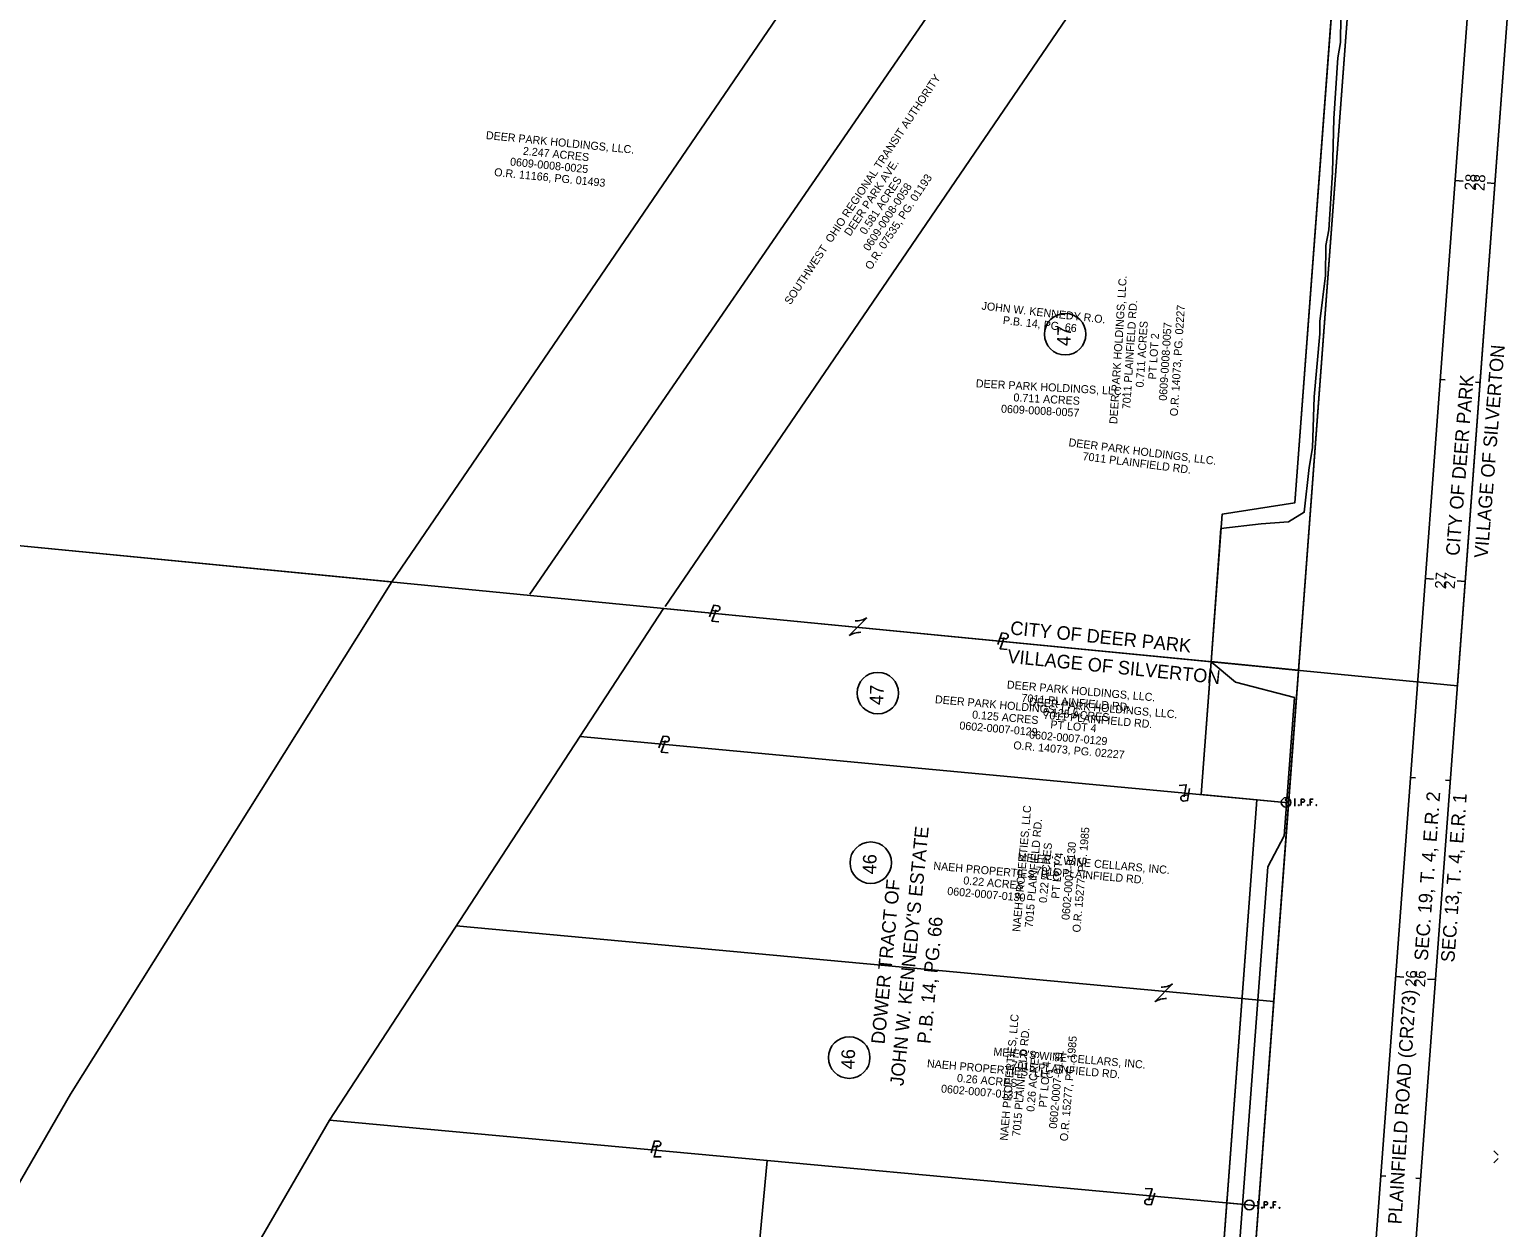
# Model space of a CAD drawing. Extents: x 204354 to 231038, y 361459 to 365260.
# Drawn here: x 220294.5 to 220662.5, y 363095.8 to 363396 of the extents above; entities that cross this region are included whole.
import ezdxf

# ---------------------------------------------------------------- set-up
doc = ezdxf.new("R2010")
doc.units = 0
for name, color, linetype in [('CM_Corridor_Point_Control', 7, 'Continuous'), ('CM_Corridor_Range_Conceptual', 7, 'Continuous'), ('Default', 7, 'Continuous'), ('DT_P_Contour_Minor', 7, 'Continuous'), ('DT_P_Contour_Text', 7, 'Continuous'), ('DT_P_Triangles', 7, 'Continuous'), ('DT_P_Void', 7, 'Continuous'), ('DT_X_Contour_Minor', 7, 'Continuous'), ('MD_P_CURB_BACK_BOT', 7, 'Continuous'), ('MD_P_Intersection_MatchLine', 7, 'Continuous'), ('MD_P_Surface_Asphalt_Concrete_Base', 7, 'Continuous'), ('MD_P_Surface_Asphalt_Concrete_Intermediate_Course', 7, 'Continuous'), ('MD_P_Surface_Finished_Grade', 7, 'Continuous'), ('MD_P_SW_BOT', 7, 'Continuous'), ('MD_P_SW_TOP', 7, 'Continuous'), ('PV_P_Curb', 7, 'Continuous'), ('PV_P_EOP', 7, 'Continuous'), ('PV_P_Walk', 7, 'Continuous'), ('SC_Shading1', 7, 'Continuous')]:
    doc.layers.add(name, color=color, linetype=linetype)

msp = doc.modelspace()

# ---------------------------------------------------------------- linework, layer by layer
at = {"layer": 'CM_Corridor_Range_Conceptual'}
for q in [(220713.48, 364052.43), (220697.45, 363837.56)]:
    msp.add_line((220572.38, 362161.22), q, dxfattribs=at)
at = {"layer": 'Default'}
msp.add_line((220562.24, 362159.63), (220675.24, 363674.28), dxfattribs=at)
at = {"layer": 'DT_P_Contour_Text'}
for centre in [(220553.98, 363319.59), (220507.05, 363229.68), (220505.28, 363187.2), (220499.88, 363138.37)]:
    msp.add_circle(centre, 5.2, dxfattribs=at)
at = {"layer": 'DT_P_Triangles'}
msp.add_lwpolyline([(220623.04, 363399.23), (220622.97, 363392.65), (220622.23, 363388.84), (220621.3, 363373.66), (220620.92, 363360.07), (220620.04, 363345.75), (220619.25, 363341.79), (220619.14, 363334.27), (220617.73, 363322.8), (220617.8, 363319.71), (220616.37, 363303.87), (220615.88, 363291.11), (220615.07, 363286.19), (220613.87, 363275), (220609.92, 363272.56), (220603.08, 363272.1), (220593, 363270.9), (220590.51, 363237.55), (220596.67, 363232.4), (220611.41, 363228.61), (220608.82, 363193.91), (220604.73, 363186.19), (220595.67, 363064.69)], dxfattribs=at)
at = {"layer": 'MD_P_CURB_BACK_BOT'}
for p, q in [((220661.62, 363357.35), (220659.63, 363357.49)), ((220657.9, 363307.48), (220656.71, 363307.57)), ((220654.18, 363257.62), (220652.19, 363257.77)), ((220650.46, 363207.76), (220649.27, 363207.85)), ((220646.74, 363157.9), (220644.75, 363158.05)), ((220643.02, 363108.04), (220641.83, 363108.13))]:
    msp.add_line(p, q, dxfattribs=at)
at = {"layer": 'MD_P_Intersection_MatchLine'}
for p, q in [((220611.53, 363277.39), (220626.27, 363475)), ((220611.53, 363277.39), (220626.27, 363475)), ((220593.27, 363274.47), (220611.53, 363277.39)), ((220590.51, 363237.47), (220593.27, 363274.47)), ((220588.03, 363204.27), (220590.51, 363237.56)), ((220612.41, 363235.32), (220590.51, 363237.56)), ((220612.41, 363235.42), (220590.52, 363237.56)), ((220588.03, 363204.27), (220609.94, 363202.23)), ((220594.43, 363101.93), (220601.97, 363202.98)), ((220594.43, 363101.93), (220601.97, 363202.97)), ((220589.36, 363033.98), (220594.53, 363103.29)), ((220594.43, 363101.95), (220602.4, 363101.21))]:
    msp.add_line(p, q, dxfattribs=at)
at = {"layer": 'MD_P_Surface_Asphalt_Concrete_Base'}
for p, q in [((220661.32, 363115.01), (220662.42, 363113.92)), ((220661.32, 363111.99), (220662.42, 363113.09))]:
    msp.add_line(p, q, dxfattribs=at)
at = {"layer": 'MD_P_Surface_Asphalt_Concrete_Intermediate_Course'}
for p, q in [((220652.24, 363231.63), (220712.17, 364034.87)), ((220048.52, 363290.31), (220652.24, 363231.54))]:
    msp.add_line(p, q, dxfattribs=at)
at = {"layer": 'MD_P_Surface_Finished_Grade'}
msp.add_line((220609.3, 363202.42), (220609.3, 363201.53), dxfattribs=at)
for points in [[(220611.33, 363203.1), (220611.69, 363203.1)], [(220611.51, 363201.5), (220611.51, 363203.1)], [(220613.08, 363201.5), (220613.08, 363203.1), (220613.61, 363203.1), (220613.66, 363203.09), (220613.74, 363203.06), (220613.77, 363203.04), (220613.8, 363203.01), (220613.85, 363202.95), (220613.88, 363202.89), (220613.9, 363202.78), (220613.9, 363202.63), (220613.89, 363202.58), (220613.87, 363202.51), (220613.83, 363202.42), (220613.78, 363202.38), (220613.75, 363202.36), (220613.69, 363202.33), (220613.61, 363202.32), (220613.08, 363202.32)], [(220616.09, 363203.1), (220615.32, 363203.1), (220615.32, 363201.5)], [(220611.33, 363201.5), (220611.69, 363201.5)], [(220612.47, 363201.71), (220612.52, 363201.71), (220612.56, 363201.69), (220612.59, 363201.64), (220612.59, 363201.58), (220612.56, 363201.53), (220612.52, 363201.5), (220612.47, 363201.5), (220612.44, 363201.53), (220612.4, 363201.58), (220612.4, 363201.64), (220612.44, 363201.69), (220612.47, 363201.71)], [(220614.72, 363201.71), (220614.77, 363201.71), (220614.81, 363201.69), (220614.84, 363201.64), (220614.84, 363201.58), (220614.81, 363201.53), (220614.77, 363201.5), (220614.72, 363201.5), (220614.69, 363201.53), (220614.65, 363201.58), (220614.65, 363201.64), (220614.69, 363201.69), (220614.72, 363201.71)], [(220615.32, 363202.32), (220615.86, 363202.32)], [(220616.87, 363201.71), (220616.92, 363201.71), (220616.96, 363201.69), (220616.99, 363201.64), (220616.99, 363201.58), (220616.96, 363201.53), (220616.92, 363201.5), (220616.87, 363201.5), (220616.83, 363201.53), (220616.8, 363201.58), (220616.8, 363201.64), (220616.83, 363201.69), (220616.87, 363201.71)], [(220602.1, 363102.24), (220602.46, 363102.24)], [(220602.1, 363100.64), (220602.46, 363100.64)], [(220602.28, 363100.64), (220602.28, 363102.24)], [(220603.24, 363100.86), (220603.29, 363100.86), (220603.33, 363100.83), (220603.36, 363100.78), (220603.36, 363100.72), (220603.33, 363100.67), (220603.29, 363100.64), (220603.24, 363100.64), (220603.21, 363100.67), (220603.17, 363100.72), (220603.17, 363100.78), (220603.21, 363100.83), (220603.24, 363100.86)], [(220603.85, 363100.64), (220603.85, 363102.24), (220604.37, 363102.24), (220604.43, 363102.23), (220604.51, 363102.2), (220604.54, 363102.18), (220604.57, 363102.15), (220604.62, 363102.09), (220604.65, 363102.03), (220604.67, 363101.93), (220604.67, 363101.77), (220604.66, 363101.72), (220604.64, 363101.65), (220604.59, 363101.56), (220604.55, 363101.52), (220604.52, 363101.5), (220604.46, 363101.47), (220604.37, 363101.46), (220603.85, 363101.46)], [(220605.49, 363100.86), (220605.54, 363100.86), (220605.58, 363100.83), (220605.61, 363100.78), (220605.61, 363100.72), (220605.58, 363100.67), (220605.54, 363100.64), (220605.49, 363100.64), (220605.45, 363100.67), (220605.42, 363100.72), (220605.42, 363100.78), (220605.45, 363100.83), (220605.49, 363100.86)], [(220606.85, 363102.24), (220606.09, 363102.24), (220606.09, 363100.64)], [(220606.09, 363101.46), (220606.63, 363101.46)], [(220607.64, 363100.86), (220607.69, 363100.86), (220607.73, 363100.83), (220607.76, 363100.78), (220607.76, 363100.72), (220607.73, 363100.67), (220607.69, 363100.64), (220607.64, 363100.64), (220607.6, 363100.67), (220607.57, 363100.72), (220607.57, 363100.78), (220607.6, 363100.83), (220607.64, 363100.86)]]:
    msp.add_lwpolyline(points, dxfattribs=at)
for centre, radius in [((220609.3, 363202.3), 1.2), ((220609.3, 363202.95), 0.16), ((220600.09, 363101.44), 1.2)]:
    msp.add_circle(centre, radius, dxfattribs=at)
at = {"layer": 'MD_P_SW_BOT'}
for p, q in [((220419.9, 363254.43), (221038.63, 364154.27)), ((220539.49, 363483.57), (220385.28, 363257.52)), ((220385.28, 363257.52), (220048.52, 363290.31)), ((220304.86, 363129.22), (220385.28, 363257.52)), ((220369.71, 363122.72), (220453.4, 363250.9)), ((220453.4, 363250.9), (220612.41, 363235.42)), ((220465.47, 363250.34), (220466.76, 363250.22)), ((220466.21, 363249.65), (220466.21, 363249.65)), ((220499.88, 363244.13), (220504.29, 363248.56)), ((220502.09, 363246.34), (220502.09, 363246.34)), ((220537.64, 363243.42), (220538.93, 363243.3)), ((220538.38, 363242.72), (220538.38, 363242.72)), ((220432.47, 363218.83), (220609.94, 363202.23)), ((220452.75, 363217.56), (220454.04, 363217.44)), ((220453.49, 363216.86), (220453.49, 363216.86)), ((220584.84, 363204.16), (220583.55, 363204.02)), ((220583.98, 363204.69), (220583.98, 363204.69)), ((220609.3, 363202.28), (220609.3, 363202.28)), ((220609.3, 363202.28), (220609.3, 363202.28)), ((220401.45, 363171.34), (220606.23, 363152.41)), ((220576.47, 363152.37), (220580.87, 363156.81)), ((220578.67, 363154.59), (220578.67, 363154.59)), ((220249.65, 363033.9), (220304.86, 363129.22)), ((220314.5, 363027.41), (220369.71, 363122.72)), ((220369.71, 363122.72), (220479.32, 363112.59)), ((220450.72, 363116.1), (220452.02, 363116.1)), ((220451.52, 363115.47), (220451.52, 363115.47)), ((220479.32, 363112.59), (220469.96, 363013.04)), ((220469.97, 363013.04), (220479.32, 363112.59)), ((220479.32, 363112.59), (220602.4, 363101.21)), ((220575.15, 363103.5), (220575.15, 363103.5)), ((220575.92, 363102.84), (220574.62, 363102.9))]:
    msp.add_line(p, q, dxfattribs=at)
for points in [[(220464.9, 363248.8), (220465.95, 363251.68), (220466.98, 363251.58)], [(220466.56, 363250.58), (220465.5, 363247.71), (220467.24, 363247.55)], [(220537.07, 363241.87), (220538.13, 363244.75), (220539.16, 363244.65)], [(220538.73, 363243.65), (220537.67, 363240.78), (220539.41, 363240.62)], [(220452.18, 363216.01), (220453.24, 363218.89), (220454.27, 363218.79)], [(220453.84, 363217.79), (220452.78, 363214.92), (220454.52, 363214.76)], [(220583.81, 363203.71), (220584.29, 363206.74), (220582.55, 363206.55)], [(220585.09, 363205.79), (220584.62, 363202.76), (220583.6, 363202.65)], [(220450.3, 363114.5), (220451.08, 363117.47), (220452.12, 363117.47)], [(220451.79, 363116.43), (220451, 363113.48), (220452.75, 363113.48)], [(220574.84, 363102.55), (220575.77, 363105.47), (220574.03, 363105.55)], [(220576.42, 363104.41), (220575.49, 363101.49), (220574.46, 363101.54)]]:
    msp.add_lwpolyline(points, dxfattribs=at)
for centre, radius, start, end in [((220466.82, 363250.91), 0.69, 265.1255, 75.9826), ((220501.51, 363253.12), 5.34, 268.6923, 301.3348), ((220502.66, 363239.57), 5.34, 88.6923, 121.3348), ((220538.99, 363243.98), 0.69, 265.1255, 75.9826), ((220454.1, 363218.13), 0.69, 265.1255, 75.9826), ((220583.63, 363203.34), 0.69, 96.5527, 267.4099), ((220578.1, 363161.37), 5.34, 268.6923, 301.3348), ((220579.25, 363147.82), 5.34, 88.6923, 121.3348), ((220452.01, 363116.78), 0.69, 270.471, 81.3281), ((220574.6, 363102.21), 0.69, 87.7036, 258.5607)]:
    msp.add_arc(centre, radius, start, end, dxfattribs=at)
at = {"layer": 'MD_P_SW_TOP'}
for q in [(220721.25, 364156.95), (220705.22, 363942.07)]:
    msp.add_line((220580.15, 362265.73), q, dxfattribs=at)
at = {"layer": 'PV_P_Curb'}
msp.add_line((220562.24, 362159.63), (220675.24, 363674.28), dxfattribs=at)
at = {"layer": 'PV_P_EOP'}
for p, q in [((220651.65, 363358.1), (220653.64, 363357.95)), ((220647.93, 363308.24), (220649.13, 363308.15)), ((220644.21, 363258.38), (220646.2, 363258.23)), ((220640.49, 363208.52), (220641.69, 363208.43)), ((220636.77, 363158.65), (220638.76, 363158.51)), ((220633.05, 363108.79), (220634.25, 363108.7))]:
    msp.add_line(p, q, dxfattribs=at)
at = {"layer": 'PV_P_Walk'}
for p, q in [((220385.28, 363257.52), (220661.37, 363662.21)), ((220653.75, 363544.57), (220453.75, 363251.41)), ((220534.47, 362190.67), (220633.24, 363514.5))]:
    msp.add_line(p, q, dxfattribs=at)
at = {"layer": 'SC_Shading1'}
msp.add_line((220602.4, 363101.21), (220594.43, 363101.95), dxfattribs=at)
for points in [[(220612.41, 363235.42), (220590.51, 363237.55), (220593.27, 363274.47), (220611.53, 363277.38), (220626.28, 363475.02), (220630.26, 363474.61)], [(220609.94, 363202.23), (220588.03, 363204.27), (220590.52, 363237.55), (220612.41, 363235.42)], [(220602.4, 363101.21), (220594.43, 363101.95), (220601.97, 363202.97), (220609.94, 363202.23)], [(220594.96, 363001.49), (220570.06, 363003.79), (220589.36, 363033.98), (220594.43, 363101.95), (220602.4, 363101.21)]]:
    msp.add_lwpolyline(points, close=True, dxfattribs=at)

# ---------------------------------------------------------------- texts
at = {"layer": 'CM_Corridor_Point_Control'}
for s, rotation, p in [('JOHN W. KENNEDY R.O.', 353.5833, (220532.95, 363325.77)), ('P.B. 14, PG. 66', 353.5833, (220538.29, 363322.16)), ('DEER PARK HOLDINGS, LLC.', 352.7474, (220554.74, 363291.55)), ('7011 PLAINFIELD RD.', 352.7474, (220558.24, 363288.08)), ('DEER PARK HOLDINGS, LLC.', 355, (220544.84, 363226.6)), ('7011 PLAINFIELD RD.', 355, (220548.48, 363223.27)), ("MEIER'S WINE CELLARS, INC.", 355, (220541.98, 363187.68)), ('7015 PLAINFIELD RD.', 355, (220546.49, 363184.27)), ("MEIER'S WINE CELLARS, INC.", 355, (220535.93, 363138.91)), ('7015 PLAINFIELD RD.', 355, (220540.45, 363135.51))]:
    msp.add_text(s, height=2, rotation=rotation, dxfattribs=at).set_placement(p)
at = {"layer": 'DT_P_Contour_Minor'}
for s, height, rotation, p in [('SOUTHWEST  OHIO REGIONAL TRANSIT AUTHORITY', 2, 56.5137, (220485.17, 363326.83)), ('DEER PARK HOLDINGS, LLC.', 2, 354.3384, (220408.81, 363368.5)), (' 2.247 ACRES', 2, 354.3384, (220417.33, 363364.64)), ('O.R. 11166, PG. 01493', 2, 354.3384, (220410.88, 363359.25)), ('0609-0008-0025', 2, 354.3384, (220414.86, 363361.87)), ('DEER PARK AVE.', 2, 56.5137, (220500.12, 363343.99)), (' 0.581 ACRES', 2, 56.5137, (220503.57, 363343.76)), ('0609-0008-0058', 2, 56.5137, (220504.85, 363340.26)), ('O.R. 07535, PG. 01193', 2, 56.5137, (220505.33, 363335.55)), ('DEER PARK HOLDINGS, LLC.', 2, 86.2864, (220567, 363297.03)), ('7011 PLAINFIELD RD.', 2, 86.2864, (220570.25, 363300.74)), ('O.R. 14073, PG. 02227', 2, 86.2864, (220582.16, 363298.99)), (' 0.711 ACRES', 2, 86.2864, (220573.56, 363305.47)), ('0609-0008-0057', 2, 86.2864, (220579.4, 363302.88)), ('PT LOT 2', 2, 86.2864, (220576.74, 363308.2)), ('VILLAGE OF SILVERTON', 3.4, 85.3966, (220659.79, 363263.4)), ('CITY OF DEER PARK', 3.4, 85.3966, (220652.68, 363263.98)), ('CITY OF DEER PARK', 3.4, 354.2396, (220540.1, 363244.39)), ('VILLAGE OF SILVERTON', 3.4, 354.2396, (220539.38, 363237.3)), ('DEER PARK HOLDINGS, LLC.', 2, 355, (220539.31, 363230.86)), ('7011 PLAINFIELD RD.', 2, 355, (220542.95, 363227.53)), (' 0.125 ACRES', 2, 355, (220547.61, 363224.11)), ('PT LOT 4', 2, 355, (220550.21, 363220.87)), ('O.R. 14073, PG. 02227', 2, 355, (220540.93, 363215.66)), ('0602-0007-0129', 2, 355, (220544.89, 363218.32)), ('SEC. 19, T. 4, E.R. 2', 3.4, 85.7455, (220644.79, 363162.55)), ('SEC. 13, T. 4, E.R. 1', 3.4, 85.7455, (220651.44, 363162.15)), ('NAEH PROPERTIES, LLC', 2, 85, (220542.71, 363169.81)), ("JOHN W. KENNEDY'S ESTATE", 3.4, 84.4086, (220513.47, 363131.19)), ('7015 PLAINFIELD RD.', 2, 85, (220545.82, 363170.85)), ('O.R. 15277, PG. 1985', 2, 85, (220557.76, 363169.65)), (' 0.22 ACRES', 2, 85, (220549.3, 363176.3)), ('0602-0007-0130', 2, 85, (220555.02, 363172.77)), ('PT LOT 4', 2, 85, (220552.47, 363178.11)), ('DOWER TRACT OF', 3.4, 84.5785, (220508.73, 363141.63)), ('14, PG. 66', 3.4, 84.4086, (220521.22, 363151.86)), ('P.B.', 3.4, 84.4086, (220520.23, 363141.71)), ('NAEH PROPERTIES, LLC', 2, 85, (220539.57, 363117.5)), ('7015 PLAINFIELD RD.', 2, 85, (220542.67, 363118.54)), ('O.R. 15277, PG. 1985', 2, 85, (220554.61, 363117.35)), (' 0.26 ACRES', 2, 85, (220546.16, 363124)), ('PT LOT 4', 2, 85, (220549.33, 363125.8)), ('0602-0007-0131', 2, 85, (220551.88, 363120.49))]:
    msp.add_text(s, height=height, rotation=rotation, dxfattribs=at).set_placement(p)
at = {"layer": 'DT_P_Contour_Text'}
for s, p in [('47', (220555.31, 363316.56)), ('47', (220508.38, 363226.65)), ('46', (220506.61, 363184.24)), ('46', (220501.22, 363135.41))]:
    msp.add_text(s, height=3.4, rotation=88.3143, dxfattribs=at).set_placement(p)
at = {"layer": 'DT_P_Void'}
msp.add_text(' PLAINFIELD ROAD (CR273)', height=3.4, rotation=86.4054, dxfattribs=at).set_placement((220638.11, 363095.28))
at = {"layer": 'DT_X_Contour_Minor'}
for s, rotation, p in [('DEER PARK HOLDINGS, LLC.', 356.9163, (220531.55, 363306.3)), (' 0.711 ACRES', 356.9163, (220540.23, 363302.83)), ('0609-0008-0057', 356.9163, (220537.86, 363299.95)), ('DEER PARK HOLDINGS, LLC.', 355, (220521.3, 363227.17)), (' 0.125 ACRES', 355, (220529.86, 363223.41)), ('0602-0007-0129', 355, (220527.41, 363220.61)), ('NAEH PROPERTIES, LLC', 355, (220520.9, 363185.46)), ('0602-0007-0130', 355, (220524.38, 363179.13)), (' 0.22 ACRES', 355, (220527.66, 363181.86)), ('NAEH PROPERTIES, LLC', 355, (220519.3, 363135.96)), (' 0.26 ACRES', 355, (220526.06, 363132.36)), ('0602-0007-0131', 355, (220522.81, 363129.63))]:
    msp.add_text(s, height=2, rotation=rotation, dxfattribs=at).set_placement(p)
at = {"layer": 'MD_P_CURB_BACK_BOT'}
for s, p in [('28', (220658.97, 363355.4)), ('27', (220651.53, 363255.69)), ('26', (220644.09, 363155.95))]:
    msp.add_text(s, height=2.8, rotation=85.7333, dxfattribs=at).set_placement(p)
at = {"layer": 'PV_P_EOP'}
for s, p in [('28', (220656.77, 363355.49)), ('27', (220649.32, 363255.69)), ('26', (220641.89, 363156.02))]:
    msp.add_text(s, height=2.8, rotation=85.7333, dxfattribs=at).set_placement(p)

doc.saveas('drawing.dxf')
